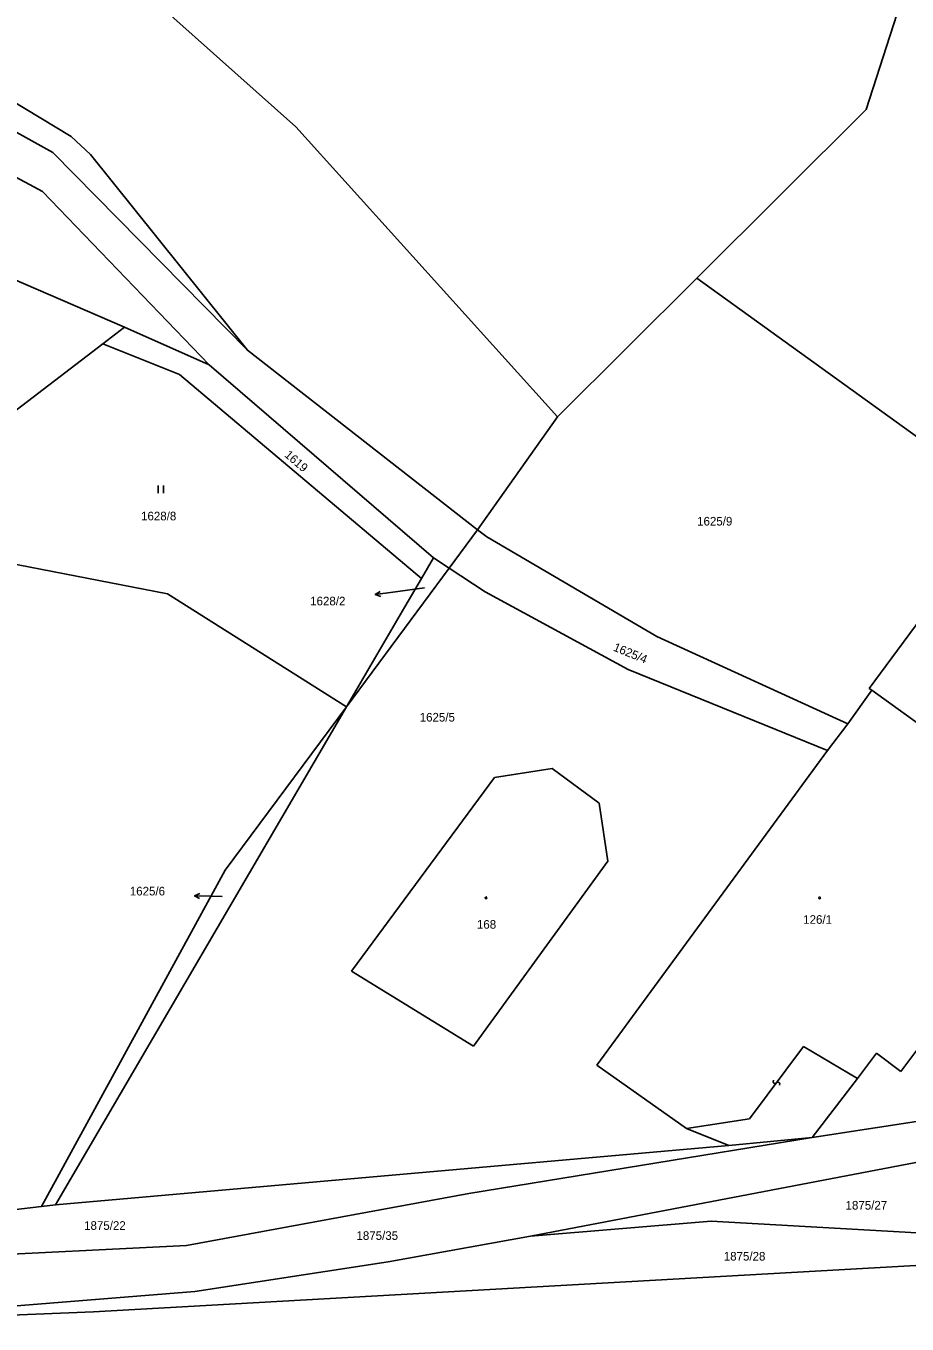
# Model space of a CAD drawing. Extents: x -747792 to -745414, y -1093712 to -1091463.
# Drawn here: x -747209.9 to -747123, y -1092151.4 to -1092023.4 of the extents above; entities that cross this region are included whole.
import ezdxf

# ---------------------------------------------------------------- set-up
doc = ezdxf.new("R2010")
doc.units = 0
for name, color, linetype in [('Pracovní_bod JDTM STC_VC', 7, 'Continuous'), ('Pracovní_bod JDTM STC_VC - výška', 7, 'Continuous'), ('Pracovní_bod JDTM STC_VC - číslo', 7, 'Continuous'), ('Pracovní_bod NN - výška', 7, 'Continuous'), ('Pracovní_bod polohopisu', 7, 'Continuous'), ('Pracovní_bod polohopisu - výška', 7, 'Continuous')]:
    doc.layers.add(name, color=color, linetype=linetype)

msp = doc.modelspace()

# ---------------------------------------------------------------- linework, layer by layer
at = {"layer": 'Pracovní_bod JDTM STC_VC - výška'}
for points in [[(-747164.54, -1092109.32), (-747164.49, -1092109.33), (-747164.47, -1092109.38), (-747164.46, -1092109.41), (-747164.47, -1092109.46), (-747164.51, -1092109.49), (-747164.54, -1092109.49), (-747164.58, -1092109.48), (-747164.61, -1092109.45), (-747164.62, -1092109.41), (-747164.61, -1092109.36), (-747164.58, -1092109.33)], [(-747131.62, -1092109.32), (-747131.57, -1092109.33), (-747131.54, -1092109.38), (-747131.53, -1092109.41), (-747131.54, -1092109.46), (-747131.58, -1092109.49), (-747131.62, -1092109.49), (-747131.67, -1092109.48), (-747131.7, -1092109.45), (-747131.71, -1092109.41), (-747131.7, -1092109.36), (-747131.66, -1092109.33)]]:
    msp.add_lwpolyline(points, close=True, dxfattribs=at)
at = {"layer": 'Pracovní_bod JDTM STC_VC - číslo'}
for points in [[(-747196.88, -1092068.73), (-747196.88, -1092069.48)], [(-747196.38, -1092069.48), (-747196.38, -1092068.73)]]:
    msp.add_lwpolyline(points, dxfattribs=at)
at = {"layer": 'Pracovní_bod NN - výška'}
for points in [[(-747120.96, -1092012.87), (-747127.01, -1092031.66)], [(-747203.47, -1092015.38), (-747183.31, -1092033.37)], [(-747251.1, -1092016.73), (-747208.29, -1092039.75)], [(-747207.3, -1092035.89), (-747219.39, -1092029.19)], [(-747205.49, -1092034.31), (-747211.48, -1092030.71)], [(-747143.72, -1092048.29), (-747127.01, -1092031.66)], [(-747183.31, -1092033.37), (-747157.47, -1092061.98)], [(-747203.58, -1092036.09), (-747205.49, -1092034.31)], [(-747188.08, -1092055.4), (-747207.3, -1092035.89)], [(-747203.58, -1092036.09), (-747188.08, -1092055.4)], [(-747191.85, -1092056.84), (-747208.29, -1092039.75)], [(-747200.22, -1092053.14), (-747215.07, -1092046.72)], [(-747157.47, -1092061.98), (-747143.72, -1092048.29)], [(-747143.72, -1092048.29), (-747113.1, -1092070.36)], [(-747200.22, -1092053.14), (-747202.36, -1092054.78)], [(-747191.85, -1092056.84), (-747200.22, -1092053.14)], [(-747202.36, -1092054.78), (-747227.92, -1092074.29)], [(-747194.8, -1092057.8), (-747202.36, -1092054.78)], [(-747165.36, -1092073.11), (-747188.08, -1092055.4)], [(-747169.72, -1092075.88), (-747191.85, -1092056.84)], [(-747170.91, -1092077.91), (-747194.8, -1092057.8)], [(-747157.47, -1092061.98), (-747165.36, -1092073.11)], [(-747113.1, -1092070.36), (-747126.72, -1092088.75)], [(-747165.36, -1092073.11), (-747168.17, -1092076.9)], [(-747164.46, -1092073.81), (-747165.36, -1092073.11)], [(-747147.69, -1092083.64), (-747164.46, -1092073.81)], [(-747195.96, -1092079.44), (-747222.08, -1092074.35)], [(-747169.72, -1092075.88), (-747170.91, -1092077.91)], [(-747169.72, -1092075.88), (-747168.17, -1092076.9)], [(-747168.17, -1092076.9), (-747178.3, -1092090.57)], [(-747168.17, -1092076.9), (-747164.61, -1092079.24)], [(-747170.91, -1092077.91), (-747172.54, -1092080.72)], [(-747178.3, -1092090.57), (-747195.96, -1092079.44)], [(-747164.61, -1092079.24), (-747150.51, -1092086.89)], [(-747172.54, -1092080.72), (-747178.3, -1092090.57)], [(-747128.84, -1092092.24), (-747147.69, -1092083.64)], [(-747150.51, -1092086.89), (-747130.84, -1092094.88)], [(-747128.84, -1092092.24), (-747126.47, -1092088.92)], [(-747126.47, -1092088.92), (-747126.72, -1092088.75)], [(-747113.84, -1092098.04), (-747126.47, -1092088.92)], [(-747178.3, -1092090.57), (-747207.03, -1092139.68)], [(-747190.27, -1092106.67), (-747178.3, -1092090.57)], [(-747130.84, -1092094.88), (-747128.84, -1092092.24)], [(-747153.61, -1092125.9), (-747130.84, -1092094.88)], [(-747158.02, -1092096.65), (-747163.69, -1092097.53)], [(-747153.37, -1092100.07), (-747158.02, -1092096.65)], [(-747163.69, -1092097.53), (-747177.82, -1092116.64)], [(-747152.5, -1092105.8), (-747153.37, -1092100.07)], [(-747165.78, -1092124.03), (-747152.5, -1092105.8)], [(-747208.4, -1092139.84), (-747190.27, -1092106.67)], [(-747177.82, -1092116.64), (-747165.78, -1092124.03)], [(-747123.61, -1092126.53), (-747118.85, -1092120.21)], [(-747127.87, -1092127.24), (-747126.01, -1092124.73)], [(-747126.01, -1092124.73), (-747123.61, -1092126.53)], [(-747144.76, -1092132.15), (-747153.61, -1092125.9)], [(-747127.87, -1092127.24), (-747132.35, -1092133.04)], [(-747132.35, -1092133.04), (-747119.91, -1092131.12)], [(-747140.56, -1092133.84), (-747144.76, -1092132.15)], [(-747207.03, -1092139.68), (-747140.56, -1092133.84)], [(-747132.35, -1092133.04), (-747166.22, -1092138.57)], [(-747132.35, -1092133.04), (-747140.56, -1092133.84)], [(-747160.16, -1092142.79), (-747120.04, -1092135.1)], [(-747166.22, -1092138.57), (-747194.11, -1092143.68)], [(-747208.4, -1092139.84), (-747224.76, -1092141.77)], [(-747207.03, -1092139.68), (-747208.4, -1092139.84)], [(-747142.32, -1092141.28), (-747160.16, -1092142.79)], [(-747120.28, -1092142.53), (-747142.32, -1092141.28)], [(-747160.16, -1092142.79), (-747174.2, -1092145.31)], [(-747194.11, -1092143.68), (-747216.67, -1092144.8)], [(-747120.38, -1092145.57), (-747203.28, -1092150.22)], [(-747174.2, -1092145.31), (-747193.27, -1092148.22)], [(-747193.27, -1092148.22), (-747233.36, -1092151.44)], [(-747203.28, -1092150.22), (-747233.36, -1092151.44)]]:
    msp.add_lwpolyline(points, dxfattribs=at)
at = {"layer": 'Pracovní_bod polohopisu'}
for points in [[(-747138.53, -1092131.21), (-747133.21, -1092124.07)], [(-747127.87, -1092127.24), (-747133.21, -1092124.07)], [(-747136.16, -1092127.4), (-747136.21, -1092127.55), (-747136.12, -1092127.69), (-747135.97, -1092127.71), (-747135.76, -1092127.57), (-747135.61, -1092127.61), (-747135.53, -1092127.75), (-747135.58, -1092127.88)], [(-747144.76, -1092132.15), (-747138.53, -1092131.21)]]:
    msp.add_lwpolyline(points, dxfattribs=at)
at = {"layer": 'Pracovní_bod polohopisu - výška'}
for points in [[(-747170.59, -1092078.84), (-747173.97, -1092079.3)], [(-747174.93, -1092079.68), (-747175.46, -1092079.5), (-747174.99, -1092079.19)], [(-747175.46, -1092079.5), (-747173.97, -1092079.3)], [(-747192.81, -1092109.47), (-747193.3, -1092109.21), (-747192.79, -1092108.97)], [(-747193.3, -1092109.21), (-747191.8, -1092109.25)], [(-747190.56, -1092109.28), (-747191.8, -1092109.25)]]:
    msp.add_lwpolyline(points, dxfattribs=at)

# ---------------------------------------------------------------- texts
at = {"layer": 'Pracovní_bod JDTM STC_VC'}
for s, rotation, p in [('1619', 319.2521, (-747184.49, -1092065.83)), ('1625/4', 337.644, (-747152.05, -1092085))]:
    msp.add_text(s, height=0.85, rotation=rotation, dxfattribs=at).set_placement(p)
for s, height, p in [('1628/8', 0.85, (-747198.58, -1092072.18)), ('1625/9', 0.85, (-747143.7, -1092072.69)), ('1628/2', 0.05, (-747170.71, -1092078.84)), ('1625/5', 0.85, (-747171.08, -1092092.02)), ('1625/6', 0.05, (-747190.67, -1092109.28)), ('126/1', 0.85, (-747133.23, -1092111.97)), ('168', 0.85, (-747165.43, -1092112.45)), ('1875/27', 0.85, (-747129.05, -1092140.15)), ('1875/22', 0.85, (-747204.2, -1092142.15)), ('1875/35', 0.85, (-747177.32, -1092143.14)), ('1875/28', 0.85, (-747141.07, -1092145.18))]:
    msp.add_text(s, height=height, dxfattribs=at).set_placement(p)
at = {"layer": 'Pracovní_bod polohopisu - výška'}
for s, p in [('1628/2', (-747181.89, -1092080.56)), ('1625/6', (-747199.69, -1092109.17))]:
    msp.add_text(s, height=0.85, dxfattribs=at).set_placement(p)

doc.saveas('drawing.dxf')
